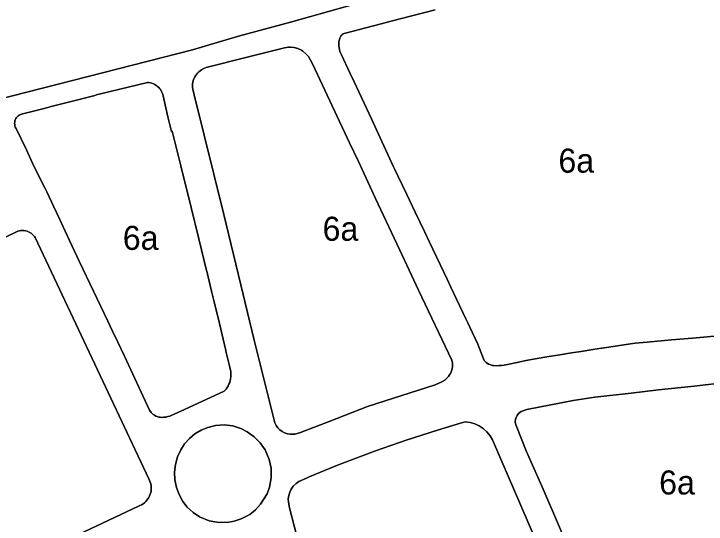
# Model space of a CAD drawing. Extents: x 598968 to 613553, y 4409678 to 4430833.
# Drawn here: x 606652.7 to 606998.6, y 4416120.7 to 4416375.4 of the extents above; entities that cross this region are included whole.
import ezdxf

# ---------------------------------------------------------------- set-up
doc = ezdxf.new("R2010")
doc.units = 0
for name, color, linetype in [('1', 7, 'Continuous'), ('Polígon industrial de Maó (naus i rafals) - ANNEX III D', 7, 'Continuous'), ('Sòl Rústic Protegit', 7, 'Continuous')]:
    doc.layers.add(name, color=color, linetype=linetype)

msp = doc.modelspace()

# ---------------------------------------------------------------- linework, layer by layer
at = {"layer": '1'}
for points in [[(606876.3512, 4416395.3537), (606790.9032, 4416371.2512), (606764.8238, 4416364.3206), (606741.8443, 4416357.4), (606628.9367, 4416328.707)], [(607026.2199, 4416216.5874), (606991.8104, 4416213.5768), (606981.2305, 4416212.6266), (606969.1007, 4416211.5464), (606963.0707, 4416210.9763), (606957.3708, 4416210.1662), (606949.9409, 4416209.0461), (606946.4309, 4416208.5261), (606946.2109, 4416208.4961), (606942.011, 4416207.826), (606936.0511, 4416206.8959), (606931.2311, 4416206.1358), (606924.5312, 4416205.0757), (606919.8812, 4416204.3056), (606913.0913, 4416203.1755), (606908.6814, 4416202.4255), (606905.5114, 4416201.7154), (606905.0114, 4416201.6054), (606898.4215, 4416200.1353), (606897.5815, 4416199.9753), (606896.3915, 4416199.8453), (606895.1916, 4416199.7953), (606893.7716, 4416199.7652), (606892.3716, 4416199.8452), (606891.8916, 4416199.9152), (606890.5316, 4416200.2952), (606889.8816, 4416200.5752), (606888.7016, 4416201.3351), (606888.1916, 4416201.8051), (606887.7316, 4416202.3451), (606885.0316, 4416209.235), (606884.4216, 4416210.5449), (606880.4516, 4416218.9848), (606879.4617, 4416221.0847), (606878.4617, 4416223.2247), (606873.8417, 4416233.0445), (606871.0317, 4416239.0344), (606869.1717, 4416242.9943), (606860.3117, 4416261.464), (606857.7717, 4416266.7738), (606853.2117, 4416276.3137), (606848.9517, 4416285.2435), (606844.6417, 4416294.2333), (606843.0717, 4416297.6132), (606842.3917, 4416299.0832), (606833.8817, 4416317.5329), (606831.2917, 4416323.0428), (606825.1617, 4416336.1025), (606822.6618, 4416341.4224), (606820.5218, 4416345.9923), (606816.2918, 4416355.0021), (606815.5618, 4416356.6721), (606815.3118, 4416357.542), (606815.0418, 4416359.352), (606815.0318, 4416360.262), (606815.1018, 4416361.172), (606815.2418, 4416362.072), (606815.5418, 4416363.272), (606816.0217, 4416364.242), (606816.3717, 4416364.662), (606816.7717, 4416365.022), (606817.2217, 4416365.332), (606818.2317, 4416365.722), (606818.4417, 4416365.762), (606845.7414, 4416372.8224), (606863.1713, 4416377.3127)], [(606515.3253, 4416200.9789), (606653.2638, 4416266.2704), (606653.9438, 4416266.6104), (606654.6638, 4416266.8905), (606655.4137, 4416267.0805), (606656.1737, 4416267.2005), (606656.9437, 4416267.2405), (606657.7137, 4416267.2005), (606658.4737, 4416267.0805), (606659.2237, 4416266.8905), (606659.9437, 4416266.6105), (606660.6337, 4416266.2706), (606661.2837, 4416265.8506), (606661.8837, 4416265.3706), (606662.4337, 4416264.8306), (606662.9237, 4416264.2306), (606663.2837, 4416263.7106), (606720.1235, 4416143.2729), (606720.5035, 4416142.4829), (606720.8135, 4416141.6629), (606721.0535, 4416140.8229), (606721.2135, 4416139.9529), (606721.2936, 4416139.0829), (606721.2836, 4416138.213), (606721.2036, 4416137.333), (606721.0436, 4416136.473), (606720.8136, 4416135.633), (606720.4936, 4416134.813), (606720.1136, 4416134.023), (606719.6536, 4416133.283), (606719.1236, 4416132.573), (606718.5436, 4416131.923), (606717.9036, 4416131.333), (606717.2036, 4416130.793), (606716.4636, 4416130.323), (606715.6836, 4416129.923), (606714.9936, 4416129.6429), (606603.6249, 4416077.1617)], [(606940.8815, 4416082.3374), (606924.2215, 4416121.5266), (606917.0815, 4416138.0663), (606912.4615, 4416148.6361), (606908.6816, 4416157.296), (606903.9001, 4416169.0232), (606903.406, 4416170.2293), (606903.1751, 4416171.6971), (606903.2824, 4416172.992), (606903.5558, 4416173.9217), (606904.0543, 4416174.8969), (606904.8015, 4416175.8557), (606906.2115, 4416176.8957), (606908.9215, 4416177.8757), (606932.1512, 4416182.4461), (606942.8611, 4416184.0463), (606961.1308, 4416186.0466), (606974.7707, 4416187.6668), (606992.6305, 4416189.5971), (607009.7402, 4416191.5874)], [(606795.3093, 4416109.5402), (606790.3594, 4416128.8145), (606789.8093, 4416131.5799), (606789.7878, 4416133.2949), (606790.0276, 4416134.9932), (606790.5231, 4416136.6353), (606791.2628, 4416138.1829), (606792.2293, 4416139.5998), (606793.7792, 4416141.0198), (606794.9892, 4416141.8998), (606798.8592, 4416143.6699), (606800.2892, 4416144.3699), (606814.2905, 4416150.1658), (606833.2787, 4416157.2403), (606848.7485, 4416162.6206), (606864.2589, 4416167.6553), (606875.7619, 4416171.0399), (606878.1283, 4416171.731), (606880.5706, 4416171.4419), (606882.9389, 4416170.7783), (606885.176, 4416169.7562), (606887.228, 4416168.4004), (606889.0453, 4416166.7432), (606890.5844, 4416164.8248), (606891.8081, 4416162.6913), (606927.3842, 4416080.1776)], [(606927.3842, 4416080.1776), (606891.8081, 4416162.6913), (606890.5844, 4416164.8248), (606889.0453, 4416166.7432), (606887.228, 4416168.4004), (606885.176, 4416169.7562), (606882.9389, 4416170.7783), (606880.5706, 4416171.4419), (606878.1283, 4416171.731), (606875.7619, 4416171.0399), (606864.2589, 4416167.6553), (606848.7485, 4416162.6206), (606833.2787, 4416157.2403), (606814.2905, 4416150.1658), (606800.2892, 4416144.3699), (606798.8592, 4416143.6699), (606794.9892, 4416141.8998), (606793.7792, 4416141.0198), (606792.2293, 4416139.5998), (606791.2628, 4416138.1829), (606790.5231, 4416136.6353), (606790.0276, 4416134.9932), (606789.7878, 4416133.2949), (606789.8093, 4416131.5799), (606790.3594, 4416128.8145), (606795.3093, 4416109.5402)]]:
    msp.add_lwpolyline(points, dxfattribs=at)
for points in [[(606793.0828, 4416165.5938), (606792.2028, 4416165.5238), (606790.7566, 4416165.5245), (606789.3288, 4416165.7554), (606787.956, 4416166.2104), (606786.6731, 4416166.8781), (606785.5128, 4416167.7414), (606784.5046, 4416168.7784), (606783.6742, 4416169.9624), (606783.0429, 4416171.2636), (606772.6087, 4416213.1636), (606767.2528, 4416235.2426), (606757.6027, 4416275.192), (606742.8126, 4416334.9211), (606742.1226, 4416337.7911), (606741.9926, 4416338.6411), (606741.9526, 4416339.5011), (606741.9926, 4416340.3711), (606742.1126, 4416341.2211), (606742.3126, 4416342.061), (606742.5826, 4416342.881), (606742.9326, 4416343.671), (606743.3526, 4416344.431), (606743.8426, 4416345.141), (606744.3926, 4416345.801), (606745.0026, 4416346.421), (606746.3725, 4416347.451), (606747.9225, 4416348.221), (606748.8125, 4416348.521), (606769.2323, 4416353.7613), (606787.9521, 4416358.4516), (606789.8421, 4416358.7216), (606790.8021, 4416358.7416), (606792.712, 4416358.5416), (606794.562, 4416358.0317), (606796.302, 4416357.2217), (606797.112, 4416356.7117), (606798.592, 4416355.4918), (606799.852, 4416354.0418), (606801.832, 4416350.3619), (606820.3819, 4416311.0027), (606824.8899, 4416301.7001), (606833.3219, 4416283.1832), (606839.9418, 4416269.1535), (606846.6518, 4416254.9338), (606854.8619, 4416237.5241), (606871.5418, 4416202.5648), (606871.8818, 4416201.0248), (606871.8218, 4416199.2648), (606871.6818, 4416198.3949), (606871.4518, 4416197.5349), (606870.7818, 4416195.9049), (606870.3319, 4416195.1449), (606869.8219, 4416194.4349), (606868.6119, 4416193.1449), (606867.9219, 4416192.5949), (606866.4219, 4416191.6848), (606863.152, 4416190.2648), (606829.4023, 4416179.3243), (606810.2725, 4416171.9141), (606795.9027, 4416166.3539)], [(606729.6728, 4416323.971), (606731.3528, 4416316.6011), (606731.7628, 4416316.7512), (606736.0328, 4416299.4914), (606741.2228, 4416278.7317), (606745.0629, 4416263.152), (606748.9729, 4416247.2522), (606749.0329, 4416247.0122), (606751.4529, 4416236.9824), (606752.7629, 4416231.5624), (606755.3629, 4416220.8226), (606758.5829, 4416207.2728), (606758.6529, 4416206.9728), (606760.393, 4416199.6329), (606760.793, 4416197.9729), (606760.993, 4416197.043), (606761.103, 4416196.103), (606761.143, 4416195.153), (606761.103, 4416194.193), (606760.983, 4416193.253), (606760.783, 4416192.323), (606760.503, 4416191.413), (606760.153, 4416190.533), (606759.723, 4416189.673), (606759.233, 4416188.863), (606758.663, 4416188.093), (606758.043, 4416187.373), (606757.783, 4416187.113), (606737.9332, 4416177.9828), (606731.3233, 4416174.9427), (606730.5733, 4416174.6527), (606729.6133, 4416174.3627), (606728.6334, 4416174.1527), (606727.6334, 4416174.0127), (606726.5934, 4416173.9626), (606725.8234, 4416174.0126), (606725.0734, 4416174.1526), (606724.3334, 4416174.3626), (606723.6234, 4416174.6526), (606722.9434, 4416175.0126), (606722.3034, 4416175.4426), (606721.7134, 4416175.9325), (606721.1834, 4416176.4825), (606720.5134, 4416177.5025), (606712.1534, 4416195.4822), (606707.8634, 4416204.602), (606704.5734, 4416211.5819), (606702.0134, 4416217.0218), (606699.6835, 4416221.9717), (606685.3335, 4416251.8611), (606679.3335, 4416264.8109), (606675.4935, 4416273.1307), (606672.4935, 4416279.4606), (606669.3435, 4416286.1305), (606668.4935, 4416287.9304), (606668.3735, 4416288.1704), (606664.6536, 4416295.3503), (606662.0336, 4416300.9102), (606659.5736, 4416306.0301), (606658.9136, 4416307.4301), (606653.7836, 4416318.1199), (606653.6636, 4416318.3099), (606653.3936, 4416318.8699), (606653.1936, 4416319.4599), (606653.0736, 4416320.0698), (606653.0336, 4416320.6998), (606653.0736, 4416321.3198), (606653.1936, 4416321.9298), (606653.3936, 4416322.5198), (606653.6636, 4416323.0798), (606654.0035, 4416323.5998), (606654.4035, 4416324.0698), (606654.8735, 4416324.4898), (606655.3835, 4416324.8498), (606655.9335, 4416325.1298), (606656.5235, 4416325.3498), (606667.7934, 4416328.18), (606671.2434, 4416329.06), (606681.3033, 4416331.5802), (606682.6832, 4416331.9302), (606686.5832, 4416332.9102), (606691.8632, 4416334.2303), (606692.5763, 4416334.4257), (606694.4986, 4416335.0803), (606695.2331, 4416335.3304), (606719.3828, 4416341.1707), (606720.1428, 4416341.1007), (606721.6428, 4416340.7007), (606722.4028, 4416340.4307), (606723.1328, 4416340.0808), (606723.8228, 4416339.6608), (606724.4728, 4416339.1808), (606725.0628, 4416338.6308), (606725.6028, 4416338.0308), (606726.0828, 4416337.3808), (606726.4928, 4416336.6908), (606726.8328, 4416335.9509), (606727.0928, 4416335.1909), (606727.2628, 4416334.5309)], [(606762.7868, 4416122.1561), (606759.197, 4416121.5261), (606754.097, 4416121.6059), (606750.2871, 4416122.3857), (606745.4772, 4416124.3355), (606742.2072, 4416126.4753), (606739.3072, 4416129.1053), (606737.0998, 4416132.049), (606735.1971, 4416135.4111), (606733.8472, 4416139.0309), (606733.0839, 4416142.8179), (606732.9261, 4416146.6779), (606733.3779, 4416150.5146), (606734.4278, 4416154.2324), (606736.0497, 4416157.7387), (606737.9754, 4416160.7562), (606740.3463, 4416163.438), (606743.1048, 4416165.7191), (606746.1842, 4416167.5441), (606749.5096, 4416168.8688), (606753.4567, 4416169.9647), (606757.7366, 4416170.2049), (606761.9966, 4416169.6851), (606766.0964, 4416168.4053), (606769.2864, 4416166.8153), (606772.7464, 4416164.3255), (606775.7364, 4416161.2857), (606778.1463, 4416157.7759), (606780.2463, 4416152.8861), (606781.1464, 4416148.5661), (606781.2464, 4416143.8263), (606780.4164, 4416139.1663), (606779.2064, 4416135.8263), (606775.9466, 4416130.5964), (606773.4166, 4416127.8863), (606770.5267, 4416125.5663), (606766.2368, 4416123.2963)], [(606762.7868, 4416122.1561), (606766.2368, 4416123.2963), (606770.5267, 4416125.5663), (606773.4166, 4416127.8863), (606775.9466, 4416130.5964), (606779.2064, 4416135.8263), (606780.4164, 4416139.1663), (606781.2464, 4416143.8263), (606781.1464, 4416148.5661), (606780.2463, 4416152.8861), (606778.1463, 4416157.7759), (606775.7364, 4416161.2857), (606772.7464, 4416164.3255), (606769.2864, 4416166.8153), (606766.0964, 4416168.4053), (606761.9966, 4416169.6851), (606757.7366, 4416170.2049), (606753.4567, 4416169.9647), (606749.5096, 4416168.8688), (606746.1842, 4416167.5441), (606743.1048, 4416165.7191), (606740.3463, 4416163.438), (606737.9754, 4416160.7562), (606736.0497, 4416157.7387), (606734.4278, 4416154.2324), (606733.3779, 4416150.5146), (606732.9261, 4416146.6779), (606733.0839, 4416142.8179), (606733.8472, 4416139.0309), (606735.1971, 4416135.4111), (606737.0998, 4416132.049), (606739.3072, 4416129.1053), (606742.2072, 4416126.4753), (606745.4772, 4416124.3355), (606750.2871, 4416122.3857), (606754.097, 4416121.6059), (606759.197, 4416121.5261)]]:
    msp.add_lwpolyline(points, close=True, dxfattribs=at)
at = {"layer": 'Polígon industrial de Maó (naus i rafals) - ANNEX III D'}
for points in [[(606863.1713, 4416377.3127), (606845.7414, 4416372.8224), (606818.4417, 4416365.762), (606818.2317, 4416365.722), (606817.2217, 4416365.332), (606816.7717, 4416365.022), (606816.3717, 4416364.662), (606816.0217, 4416364.242), (606815.5418, 4416363.272), (606815.2418, 4416362.072), (606815.1018, 4416361.172), (606815.0318, 4416360.262), (606815.0418, 4416359.352), (606815.3118, 4416357.542), (606815.5618, 4416356.6721), (606816.2918, 4416355.0021), (606820.5218, 4416345.9923), (606822.6618, 4416341.4224), (606825.1617, 4416336.1025), (606831.2917, 4416323.0428), (606833.8817, 4416317.5329), (606842.3917, 4416299.0832), (606843.0717, 4416297.6132), (606844.6417, 4416294.2333), (606848.9517, 4416285.2435), (606853.2117, 4416276.3137), (606857.7717, 4416266.7738), (606860.3117, 4416261.464), (606869.1717, 4416242.9943), (606871.0317, 4416239.0344), (606873.8417, 4416233.0445), (606878.4617, 4416223.2247), (606879.4617, 4416221.0847), (606880.4516, 4416218.9848), (606884.4216, 4416210.5449), (606885.0316, 4416209.235), (606887.7316, 4416202.3451), (606888.1916, 4416201.8051), (606888.7016, 4416201.3351), (606889.8816, 4416200.5752), (606890.5316, 4416200.2952), (606891.8916, 4416199.9152), (606892.3716, 4416199.8452), (606893.7716, 4416199.7652), (606895.1916, 4416199.7953), (606896.3915, 4416199.8453), (606897.5815, 4416199.9753), (606898.4215, 4416200.1353), (606905.0114, 4416201.6054), (606905.5114, 4416201.7154), (606908.6814, 4416202.4255), (606913.0913, 4416203.1755), (606919.8812, 4416204.3056), (606924.5312, 4416205.0757), (606931.2311, 4416206.1358), (606936.0511, 4416206.8959), (606942.011, 4416207.826), (606946.2109, 4416208.4961), (606946.4309, 4416208.5261), (606949.9409, 4416209.0461), (606957.3708, 4416210.1662), (606963.0707, 4416210.9763), (606969.1007, 4416211.5464), (606981.2305, 4416212.6266), (606991.8104, 4416213.5768), (607026.2199, 4416216.5874)], [(606603.6249, 4416077.1617), (606714.9936, 4416129.6429), (606715.6836, 4416129.923), (606716.4636, 4416130.323), (606717.2036, 4416130.793), (606717.9036, 4416131.333), (606718.5436, 4416131.923), (606719.1236, 4416132.573), (606719.6536, 4416133.283), (606720.1136, 4416134.023), (606720.4936, 4416134.813), (606720.8136, 4416135.633), (606721.0436, 4416136.473), (606721.2036, 4416137.333), (606721.2836, 4416138.213), (606721.2936, 4416139.0829), (606721.2135, 4416139.9529), (606721.0535, 4416140.8229), (606720.8135, 4416141.6629), (606720.5035, 4416142.4829), (606720.1235, 4416143.2729), (606663.2837, 4416263.7106), (606662.9237, 4416264.2306), (606662.4337, 4416264.8306), (606661.8837, 4416265.3706), (606661.2837, 4416265.8506), (606660.6337, 4416266.2706), (606659.9437, 4416266.6105), (606659.2237, 4416266.8905), (606658.4737, 4416267.0805), (606657.7137, 4416267.2005), (606656.9437, 4416267.2405), (606656.1737, 4416267.2005), (606655.4137, 4416267.0805), (606654.6638, 4416266.8905), (606653.9438, 4416266.6104), (606653.2638, 4416266.2704), (606515.3253, 4416200.9789)], [(607009.7402, 4416191.5874), (606992.6305, 4416189.5971), (606974.7707, 4416187.6668), (606961.1308, 4416186.0466), (606942.8611, 4416184.0463), (606932.1512, 4416182.4461), (606908.9215, 4416177.8757), (606906.2115, 4416176.8957), (606904.8015, 4416175.8557), (606904.0543, 4416174.8969), (606903.5558, 4416173.9217), (606903.2824, 4416172.992), (606903.1751, 4416171.6971), (606903.406, 4416170.2293), (606903.9001, 4416169.0232), (606908.6816, 4416157.296), (606912.4615, 4416148.6361), (606917.0815, 4416138.0663), (606924.2215, 4416121.5266), (606940.8815, 4416082.3374)]]:
    msp.add_lwpolyline(points, dxfattribs=at)
for points in [[(606793.0828, 4416165.5938), (606795.9027, 4416166.3539), (606810.2725, 4416171.9141), (606829.4023, 4416179.3243), (606863.152, 4416190.2648), (606866.4219, 4416191.6848), (606867.9219, 4416192.5949), (606868.6119, 4416193.1449), (606869.8219, 4416194.4349), (606870.3319, 4416195.1449), (606870.7818, 4416195.9049), (606871.4518, 4416197.5349), (606871.6818, 4416198.3949), (606871.8218, 4416199.2648), (606871.8818, 4416201.0248), (606871.5418, 4416202.5648), (606854.8619, 4416237.5241), (606846.6518, 4416254.9338), (606839.9418, 4416269.1535), (606833.3219, 4416283.1832), (606824.8899, 4416301.7001), (606820.3819, 4416311.0027), (606801.832, 4416350.3619), (606799.852, 4416354.0418), (606798.592, 4416355.4918), (606797.112, 4416356.7117), (606796.302, 4416357.2217), (606794.562, 4416358.0317), (606792.712, 4416358.5416), (606790.8021, 4416358.7416), (606789.8421, 4416358.7216), (606787.9521, 4416358.4516), (606769.2323, 4416353.7613), (606748.8125, 4416348.521), (606747.9225, 4416348.221), (606746.3725, 4416347.451), (606745.0026, 4416346.421), (606744.3926, 4416345.801), (606743.8426, 4416345.141), (606743.3526, 4416344.431), (606742.9326, 4416343.671), (606742.5826, 4416342.881), (606742.3126, 4416342.061), (606742.1126, 4416341.2211), (606741.9926, 4416340.3711), (606741.9526, 4416339.5011), (606741.9926, 4416338.6411), (606742.1226, 4416337.7911), (606742.8126, 4416334.9211), (606757.6027, 4416275.192), (606767.2528, 4416235.2426), (606772.6087, 4416213.1636), (606783.0429, 4416171.2636), (606783.6742, 4416169.9624), (606784.5046, 4416168.7784), (606785.5128, 4416167.7414), (606786.6731, 4416166.8781), (606787.956, 4416166.2104), (606789.3288, 4416165.7554), (606790.7566, 4416165.5245), (606792.2028, 4416165.5238)], [(606729.6728, 4416323.971), (606727.2628, 4416334.5309), (606727.0928, 4416335.1909), (606726.8328, 4416335.9509), (606726.4928, 4416336.6908), (606726.0828, 4416337.3808), (606725.6028, 4416338.0308), (606725.0628, 4416338.6308), (606724.4728, 4416339.1808), (606723.8228, 4416339.6608), (606723.1328, 4416340.0808), (606722.4028, 4416340.4307), (606721.6428, 4416340.7007), (606720.1428, 4416341.1007), (606719.3828, 4416341.1707), (606695.2331, 4416335.3304), (606694.4986, 4416335.0803), (606692.5763, 4416334.4257), (606691.8632, 4416334.2303), (606686.5832, 4416332.9102), (606682.6832, 4416331.9302), (606681.3033, 4416331.5802), (606671.2434, 4416329.06), (606667.7934, 4416328.18), (606656.5235, 4416325.3498), (606655.9335, 4416325.1298), (606655.3835, 4416324.8498), (606654.8735, 4416324.4898), (606654.4035, 4416324.0698), (606654.0035, 4416323.5998), (606653.6636, 4416323.0798), (606653.3936, 4416322.5198), (606653.1936, 4416321.9298), (606653.0736, 4416321.3198), (606653.0336, 4416320.6998), (606653.0736, 4416320.0698), (606653.1936, 4416319.4599), (606653.3936, 4416318.8699), (606653.6636, 4416318.3099), (606653.7836, 4416318.1199), (606658.9136, 4416307.4301), (606659.5736, 4416306.0301), (606662.0336, 4416300.9102), (606664.6536, 4416295.3503), (606668.3735, 4416288.1704), (606668.4935, 4416287.9304), (606669.3435, 4416286.1305), (606672.4935, 4416279.4606), (606675.4935, 4416273.1307), (606679.3335, 4416264.8109), (606685.3335, 4416251.8611), (606699.6835, 4416221.9717), (606702.0134, 4416217.0218), (606704.5734, 4416211.5819), (606707.8634, 4416204.602), (606712.1534, 4416195.4822), (606720.5134, 4416177.5025), (606721.1834, 4416176.4825), (606721.7134, 4416175.9325), (606722.3034, 4416175.4426), (606722.9434, 4416175.0126), (606723.6234, 4416174.6526), (606724.3334, 4416174.3626), (606725.0734, 4416174.1526), (606725.8234, 4416174.0126), (606726.5934, 4416173.9626), (606727.6334, 4416174.0127), (606728.6334, 4416174.1527), (606729.6133, 4416174.3627), (606730.5733, 4416174.6527), (606731.3233, 4416174.9427), (606737.9332, 4416177.9828), (606757.783, 4416187.113), (606758.043, 4416187.373), (606758.663, 4416188.093), (606759.233, 4416188.863), (606759.723, 4416189.673), (606760.153, 4416190.533), (606760.503, 4416191.413), (606760.783, 4416192.323), (606760.983, 4416193.253), (606761.103, 4416194.193), (606761.143, 4416195.153), (606761.103, 4416196.103), (606760.993, 4416197.043), (606760.793, 4416197.9729), (606760.393, 4416199.6329), (606758.6529, 4416206.9728), (606758.5829, 4416207.2728), (606755.3629, 4416220.8226), (606752.7629, 4416231.5624), (606751.4529, 4416236.9824), (606749.0329, 4416247.0122), (606748.9729, 4416247.2522), (606745.0629, 4416263.152), (606741.2228, 4416278.7317), (606736.0328, 4416299.4914), (606731.7628, 4416316.7512), (606731.3528, 4416316.6011)]]:
    msp.add_lwpolyline(points, close=True, dxfattribs=at)
at = {"layer": 'Sòl Rústic Protegit'}
msp.add_lwpolyline([(606628.9367, 4416328.707), (606741.8443, 4416357.4), (606764.8238, 4416364.3206), (606790.9032, 4416371.2512), (606876.3512, 4416395.3537)], dxfattribs=at)

# ---------------------------------------------------------------- texts
at = {"layer": 'Polígon industrial de Maó (naus i rafals) - ANNEX III D'}
for p in [(606924.7508, 4416296.1146), (606806.9172, 4416262.1327), (606707.0883, 4416257.5667), (606975.0776, 4416135.483)]:
    msp.add_text('6a', height=12, dxfattribs=at).set_placement(p)

doc.saveas('drawing.dxf')
